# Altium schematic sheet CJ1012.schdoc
size 127 x 101 mm
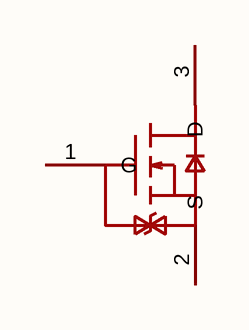
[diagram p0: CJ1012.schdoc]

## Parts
Q?  cj1012 c  [SOT-523-3_L1.6-W0.8-P1.00-LS1.6-BR]  (value not drawn)

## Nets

Not connected (* = marked no-connect by the designer): Q? 1(G) 2(S) 3(D)

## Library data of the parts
Q? = cj1012 c: 数量:1个N沟道;漏源电压(Vdss):20V;连续漏极电流(Id):500mA;导通电阻(RDS(on)):850mΩ@2.5V;耗散功率(Pd):275mW;阈值电压(Vgs(th)):1.2V;; Manufacturer: CJ(江苏长电/长晶); AddInBom: yes; ModelId: 3e7fadd59d8d474faa89c2c7e0676879; ModelName: SOT-523-3P_L1.6-W0.8-H0.9-LS1.6-P0.50; ModelTransform: 63.48633,62.992,0,180,0,0,0,0,0; Number: 1个N沟道; Drain to Source Voltage: 20V; Current - Continuous Drain(Id): 500mA; Pd - Power Dissipation: 275mW; Gate Threshold Voltage (Vgs(th)): 1.2V; Gate Charge(Qg): 750nC; Input Capacitance(Ciss): 100pF; Reverse Transfer Capacitance (Crss@Vds): 12pF; Type: N沟道; Output Capacitance(Coss): 16pF; Vgs: ±12V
